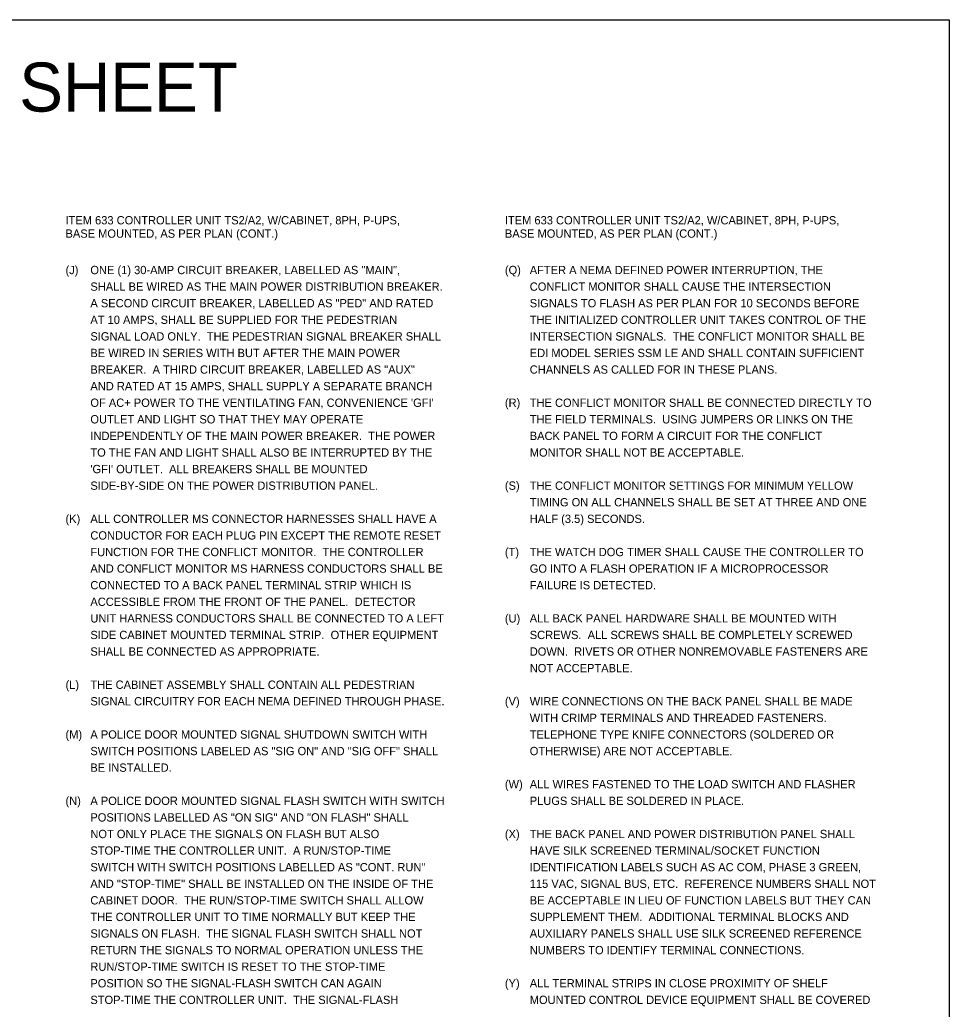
# Model space of a CAD drawing. Extents: x -27 to 74, y -37 to 38.
# Drawn here: x 58.66 to 74.35, y -19.99 to -3.29 of the extents above; entities that cross this region are included whole.
import ezdxf

# ---------------------------------------------------------------- set-up
doc = ezdxf.new("R2010")
doc.units = 0
doc.layers.add('SH_Data', color=7, linetype='Continuous')
doc.layers.add('SH_Text', color=7, linetype='Continuous')

msp = doc.modelspace()

# ---------------------------------------------------------------- linework, layer by layer
at = {"layer": 'SH_Text'}
msp.add_lwpolyline([(42.584, -3.293), (74.352, -3.293), (74.352, -36.623), (42.584, -36.623)], close=True, dxfattribs=at)

# ---------------------------------------------------------------- texts
at = {"layer": 'SH_Data'}
for s, height, p in [('PULLED OFF OF SHEET', 0.82794, (49.665, -4.843)), ('ITEM 633 CONTROLLER UNIT TS2/A2, W/CABINET, 8PH, P-UPS, ', 0.14, (59.428, -6.747)), ('ITEM 633 CONTROLLER UNIT TS2/A2, W/CABINET, 8PH, P-UPS, ', 0.14, (66.848, -6.747)), ('BASE MOUNTED, AS PER PLAN (CONT.)', 0.14, (59.428, -6.972)), ('BASE MOUNTED, AS PER PLAN (CONT.)', 0.14, (66.848, -6.972)), ('(J)', 0.14, (59.428, -7.587)), ('ONE (1) 30-AMP CIRCUIT BREAKER, LABELLED AS "MAIN", ', 0.14, (59.848, -7.587)), ('(Q)', 0.14, (66.848, -7.587)), ('AFTER A NEMA DEFINED POWER INTERRUPTION, THE ', 0.14, (67.268, -7.587)), ('SHALL BE WIRED AS THE MAIN POWER DISTRIBUTION BREAKER.  ', 0.14, (59.848, -7.867)), ('CONFLICT MONITOR SHALL CAUSE THE INTERSECTION ', 0.14, (67.268, -7.867)), ('A SECOND CIRCUIT BREAKER, LABELLED AS "PED" AND RATED ', 0.14, (59.848, -8.147)), ('SIGNALS TO FLASH AS PER PLAN FOR 10 SECONDS BEFORE ', 0.14, (67.268, -8.147)), ('AT 10 AMPS, SHALL BE SUPPLIED FOR THE PEDESTRIAN ', 0.14, (59.848, -8.427)), ('THE INITIALIZED CONTROLLER UNIT TAKES CONTROL OF THE ', 0.14, (67.268, -8.427)), ('SIGNAL LOAD ONLY.  THE PEDESTRIAN SIGNAL BREAKER SHALL ', 0.14, (59.848, -8.707)), ('INTERSECTION SIGNALS.  THE CONFLICT MONITOR SHALL BE ', 0.14, (67.268, -8.707)), ('BE WIRED IN SERIES WITH BUT AFTER THE MAIN POWER ', 0.14, (59.848, -8.987)), ('EDI MODEL SERIES SSM LE AND SHALL CONTAIN SUFFICIENT ', 0.14, (67.268, -8.987)), ('BREAKER.  A THIRD CIRCUIT BREAKER, LABELLED AS "AUX" ', 0.14, (59.848, -9.267)), ('CHANNELS AS CALLED FOR IN THESE PLANS.', 0.14, (67.268, -9.267)), ('AND RATED AT 15 AMPS, SHALL SUPPLY A SEPARATE BRANCH ', 0.14, (59.848, -9.547)), ("OF AC+ POWER TO THE VENTILATING FAN, CONVENIENCE 'GFI' ", 0.14, (59.848, -9.827)), ('(R)', 0.14, (66.848, -9.827)), ('THE CONFLICT MONITOR SHALL BE CONNECTED DIRECTLY TO ', 0.14, (67.268, -9.827)), ('OUTLET AND LIGHT SO THAT THEY MAY OPERATE ', 0.14, (59.848, -10.107)), ('THE FIELD TERMINALS.  USING JUMPERS OR LINKS ON THE ', 0.14, (67.268, -10.107)), ('INDEPENDENTLY OF THE MAIN POWER BREAKER.  THE POWER ', 0.14, (59.848, -10.387)), ('BACK PANEL TO FORM A CIRCUIT FOR THE CONFLICT ', 0.14, (67.268, -10.387)), ('TO THE FAN AND LIGHT SHALL ALSO BE INTERRUPTED BY THE ', 0.14, (59.848, -10.667)), ('MONITOR SHALL NOT BE ACCEPTABLE.', 0.14, (67.268, -10.667)), ("'GFI' OUTLET.  ALL BREAKERS SHALL BE MOUNTED ", 0.14, (59.848, -10.947)), ('SIDE-BY-SIDE ON THE POWER DISTRIBUTION PANEL.', 0.14, (59.848, -11.227)), ('(S)', 0.14, (66.848, -11.227)), ('THE CONFLICT MONITOR SETTINGS FOR MINIMUM YELLOW ', 0.14, (67.268, -11.227)), ('TIMING ON ALL CHANNELS SHALL BE SET AT THREE AND ONE ', 0.14, (67.268, -11.507)), ('(K)', 0.14, (59.428, -11.787)), ('ALL CONTROLLER MS CONNECTOR HARNESSES SHALL HAVE A ', 0.14, (59.848, -11.787)), ('HALF (3.5) SECONDS.', 0.14, (67.268, -11.787)), ('CONDUCTOR FOR EACH PLUG PIN EXCEPT THE REMOTE RESET ', 0.14, (59.848, -12.067)), ('FUNCTION FOR THE CONFLICT MONITOR.  THE CONTROLLER ', 0.14, (59.848, -12.347)), ('(T)', 0.14, (66.848, -12.347)), ('THE WATCH DOG TIMER SHALL CAUSE THE CONTROLLER TO ', 0.14, (67.268, -12.347)), ('AND CONFLICT MONITOR MS HARNESS CONDUCTORS SHALL BE ', 0.14, (59.848, -12.627)), ('GO INTO A FLASH OPERATION IF A MICROPROCESSOR ', 0.14, (67.268, -12.627)), ('CONNECTED TO A BACK PANEL TERMINAL STRIP WHICH IS ', 0.14, (59.848, -12.907)), ('FAILURE IS DETECTED.', 0.14, (67.268, -12.907)), ('ACCESSIBLE FROM THE FRONT OF THE PANEL.  DETECTOR ', 0.14, (59.848, -13.187)), ('UNIT HARNESS CONDUCTORS SHALL BE CONNECTED TO A LEFT ', 0.14, (59.848, -13.467)), ('(U)', 0.14, (66.848, -13.467)), ('ALL BACK PANEL HARDWARE SHALL BE MOUNTED WITH ', 0.14, (67.268, -13.467)), ('SIDE CABINET MOUNTED TERMINAL STRIP.  OTHER EQUIPMENT ', 0.14, (59.848, -13.747)), ('SCREWS.  ALL SCREWS SHALL BE COMPLETELY SCREWED ', 0.14, (67.268, -13.747)), ('SHALL BE CONNECTED AS APPROPRIATE.', 0.14, (59.848, -14.027)), ('DOWN.  RIVETS OR OTHER NONREMOVABLE FASTENERS ARE ', 0.14, (67.268, -14.027)), ('NOT ACCEPTABLE.', 0.14, (67.268, -14.307)), ('(L)', 0.14, (59.428, -14.587)), ('THE CABINET ASSEMBLY SHALL CONTAIN ALL PEDESTRIAN ', 0.14, (59.848, -14.587)), ('SIGNAL CIRCUITRY FOR EACH NEMA DEFINED THROUGH PHASE.', 0.14, (59.848, -14.867)), ('(V)', 0.14, (66.848, -14.867)), ('WIRE CONNECTIONS ON THE BACK PANEL SHALL BE MADE ', 0.14, (67.268, -14.867)), ('WITH CRIMP TERMINALS AND THREADED FASTENERS.  ', 0.14, (67.268, -15.147)), ('(M)', 0.14, (59.428, -15.427)), ('A POLICE DOOR MOUNTED SIGNAL SHUTDOWN SWITCH WITH ', 0.14, (59.848, -15.427)), ('TELEPHONE TYPE KNIFE CONNECTORS (SOLDERED OR ', 0.14, (67.268, -15.427)), ('SWITCH POSITIONS LABELED AS "SIG ON" AND "SIG OFF" SHALL ', 0.14, (59.848, -15.707)), ('OTHERWISE) ARE NOT ACCEPTABLE.', 0.14, (67.268, -15.707)), ('BE INSTALLED.', 0.14, (59.848, -15.987)), ('(W)', 0.14, (66.848, -16.267)), ('ALL WIRES FASTENED TO THE LOAD SWITCH AND FLASHER ', 0.14, (67.268, -16.267)), ('(N)', 0.14, (59.428, -16.547)), ('A POLICE DOOR MOUNTED SIGNAL FLASH SWITCH WITH SWITCH ', 0.14, (59.848, -16.547)), ('PLUGS SHALL BE SOLDERED IN PLACE.', 0.14, (67.268, -16.547)), ('POSITIONS LABELLED AS "ON SIG" AND "ON FLASH" SHALL ', 0.14, (59.848, -16.827)), ('NOT ONLY PLACE THE SIGNALS ON FLASH BUT ALSO ', 0.14, (59.848, -17.107)), ('(X)', 0.14, (66.848, -17.107)), ('THE BACK PANEL AND POWER DISTRIBUTION PANEL SHALL ', 0.14, (67.268, -17.107)), ('STOP-TIME THE CONTROLLER UNIT.  A RUN/STOP-TIME ', 0.14, (59.848, -17.387)), ('HAVE SILK SCREENED TERMINAL/SOCKET FUNCTION ', 0.14, (67.268, -17.387)), ('SWITCH WITH SWITCH POSITIONS LABELLED AS "CONT. RUN" ', 0.14, (59.848, -17.667)), ('IDENTIFICATION LABELS SUCH AS AC COM, PHASE 3 GREEN, ', 0.14, (67.268, -17.667)), ('AND "STOP-TIME" SHALL BE INSTALLED ON THE INSIDE OF THE ', 0.14, (59.848, -17.947)), ('115 VAC, SIGNAL BUS, ETC.  REFERENCE NUMBERS SHALL NOT ', 0.14, (67.268, -17.947)), ('CABINET DOOR.  THE RUN/STOP-TIME SWITCH SHALL ALLOW ', 0.14, (59.848, -18.227)), ('BE ACCEPTABLE IN LIEU OF FUNCTION LABELS BUT THEY CAN ', 0.14, (67.268, -18.227)), ('THE CONTROLLER UNIT TO TIME NORMALLY BUT KEEP THE ', 0.14, (59.848, -18.507)), ('SUPPLEMENT THEM.  ADDITIONAL TERMINAL BLOCKS AND ', 0.14, (67.268, -18.507)), ('SIGNALS ON FLASH.  THE SIGNAL FLASH SWITCH SHALL NOT ', 0.14, (59.848, -18.787)), ('AUXILIARY PANELS SHALL USE SILK SCREENED REFERENCE ', 0.14, (67.268, -18.787)), ('RETURN THE SIGNALS TO NORMAL OPERATION UNLESS THE ', 0.14, (59.848, -19.067)), ('NUMBERS TO IDENTIFY TERMINAL CONNECTIONS.', 0.14, (67.268, -19.067)), ('RUN/STOP-TIME SWITCH IS RESET TO THE STOP-TIME ', 0.14, (59.848, -19.347)), ('POSITION SO THE SIGNAL-FLASH SWITCH CAN AGAIN ', 0.14, (59.848, -19.627)), ('(Y)', 0.14, (66.848, -19.627)), ('ALL TERMINAL STRIPS IN CLOSE PROXIMITY OF SHELF ', 0.14, (67.268, -19.627)), ('STOP-TIME THE CONTROLLER UNIT.  THE SIGNAL-FLASH ', 0.14, (59.848, -19.907)), ('MOUNTED CONTROL DEVICE EQUIPMENT SHALL BE COVERED ', 0.14, (67.268, -19.907))]:
    msp.add_text(s, height=height, dxfattribs=at).set_placement(p)

doc.saveas('drawing.dxf')
